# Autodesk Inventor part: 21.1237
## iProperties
Created: 2006-02
Part Number: 21.1237
Material: Steel, Mild
Description: M5 x 30 SHCS
Document SubType Name: Modeling
Standard: DIN 7984
Designer: Andy Moles
Standards Organization: DIN
Language: en-US
Size Designation: M5 x 30
Categories: <MemberInstance><Categories><Category DisplayName="Fasteners" InternalName="e4da775c-781d-43d5-af7c-5136215cf5a6" Mnemonic="FSTN"><Category DisplayName="Bolts"
Density: 7.86 g/cm^3
Mass: 5.97669 g
Surface Area: 6.97701 cm^2
Volume: 0.760393 cm^3
Vendor: S
Author: Andy Moles
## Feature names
1. Body [Revolution]
2. Slot [Extrusion]
3. Fillet1
4. Chamfer1
